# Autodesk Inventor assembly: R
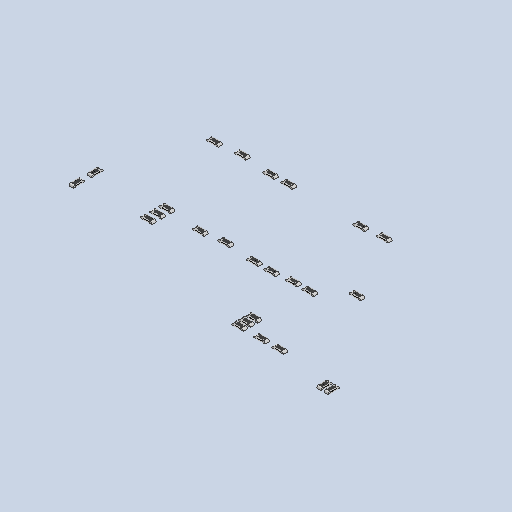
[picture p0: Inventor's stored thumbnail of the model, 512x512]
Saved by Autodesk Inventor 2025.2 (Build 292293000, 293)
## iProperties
Created: 2025-04
Part Number: R
Description: PART--DESC
Document SubType Name: Assembly
Designer: BennF
Author: BennF
Revision Number: NONE
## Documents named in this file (7)
- C:\Users\BennF\Nextcloud\Benutzer\CNC JarBeRi\existing parts\Electronics\RepRap A4988 Shied (USE WITHOUT ARDUINO)\reprap-a4988-1.snapshot.1\RepRap\RepRap\R.iam
- C:\Users\BennF\Nextcloud\Benutzer\CNC JarBeRi\existing parts\Electronics\RepRap A4988 Shied (USE WITHOUT ARDUINO)\reprap-a4988-1.snapshot.1\RepRap\RepRap\104.ipt
- C:\Users\BennF\Nextcloud\Benutzer\CNC JarBeRi\existing parts\Electronics\RepRap A4988 Shied (USE WITHOUT ARDUINO)\reprap-a4988-1.snapshot.1\RepRap\RepRap\103.ipt
- C:\Users\BennF\Nextcloud\Benutzer\CNC JarBeRi\existing parts\Electronics\RepRap A4988 Shied (USE WITHOUT ARDUINO)\reprap-a4988-1.snapshot.1\RepRap\RepRap\102.ipt
- C:\Users\BennF\Nextcloud\Benutzer\CNC JarBeRi\existing parts\Electronics\RepRap A4988 Shied (USE WITHOUT ARDUINO)\reprap-a4988-1.snapshot.1\RepRap\RepRap\10R0.ipt
- C:\Users\BennF\Nextcloud\Benutzer\CNC JarBeRi\existing parts\Electronics\RepRap A4988 Shied (USE WITHOUT ARDUINO)\reprap-a4988-1.snapshot.1\RepRap\RepRap\182.ipt
- C:\Users\BennF\Nextcloud\Benutzer\CNC JarBeRi\existing parts\Electronics\RepRap A4988 Shied (USE WITHOUT ARDUINO)\reprap-a4988-1.snapshot.1\RepRap\RepRap\472.ipt
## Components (25 placed, 6 different names)
1. 104
2. 103
3. 103:1
4. 104:1
5. 104:2
6. 102
7. 104:3
8. 104:4
9. 10R0
10. 10R0:1
11. 182
12. 182:1
13. 182:2
14. 104:5
15. 103:2
16. 104:6
17. 103:3
18. 103:4
19. 104:7
20. 472
21. 472:1
22. 472:2
23. 472:3
24. 472:4
25. 10R0:2
